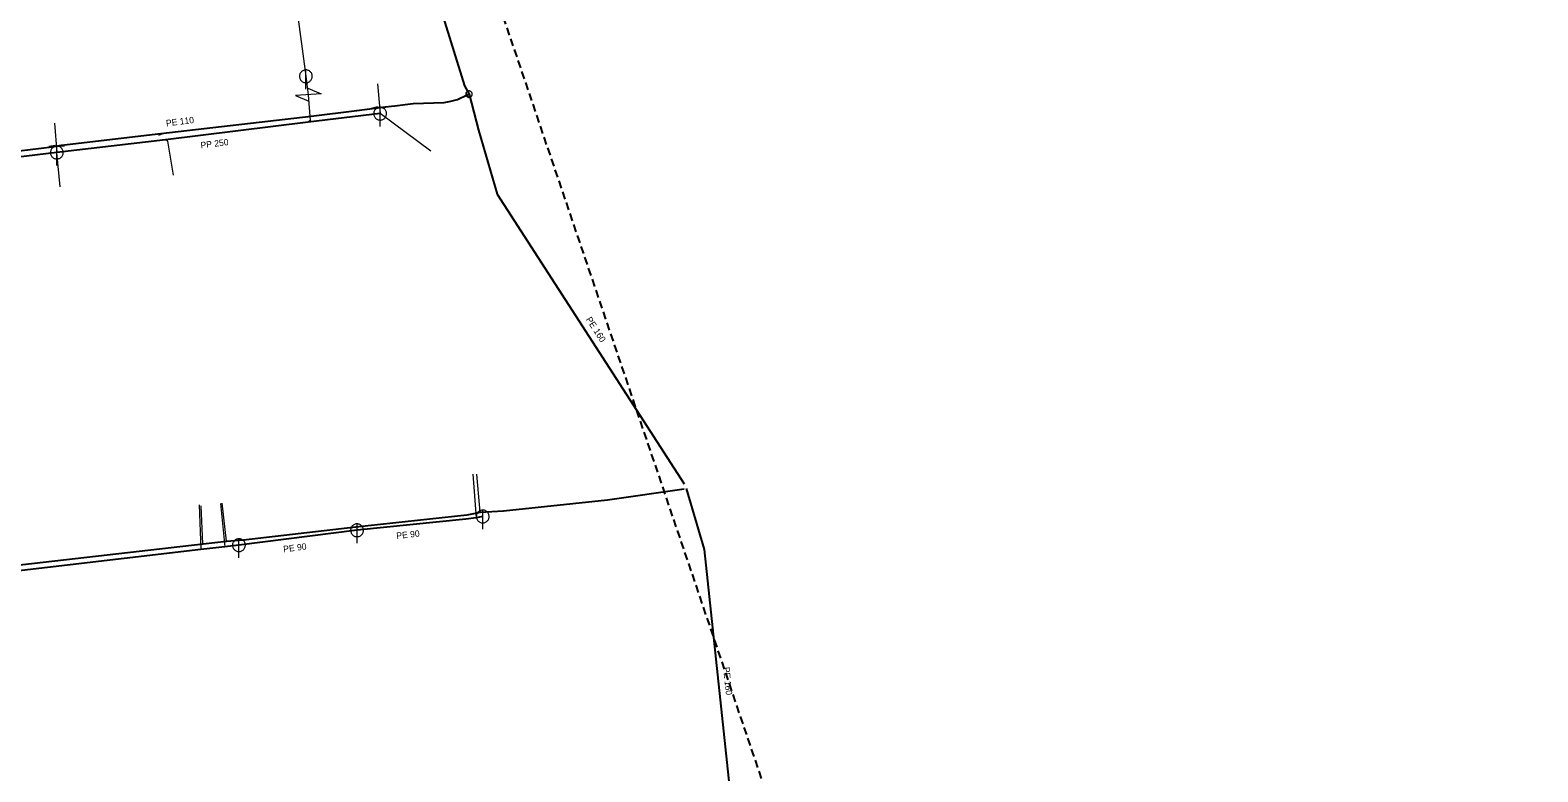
# Model space of a CAD drawing. Extents: x -659250 to -657316, y -997555 to -993684.
# Drawn here: x -658279.6 to -658044.4, y -994985.4 to -994869.8 of the extents above; entities that cross this region are included whole.
import ezdxf

# ---------------------------------------------------------------- set-up
doc = ezdxf.new("R2010")
doc.units = 0
doc.header["$LTSCALE"] = 0.4
doc.linetypes.add('MEDIUM_DASHED', pattern=[4.5, 3, -1.5])
doc.layers.add('1', color=7, linetype='Continuous')
for name, color, linetype, lineweight in [('11', 7, 'Continuous', 13), ('13', 7, 'Continuous', 13), ('14', 7, 'Continuous', 25), ('17', 7, 'Continuous', 25), ('22', 7, 'Continuous', 13), ('31', 7, 'Continuous', 13), ('34', 7, 'Continuous', 13), ('47', 7, 'Continuous', 13), ('63', 7, 'MEDIUM_DASHED', 25)]:
    doc.layers.add(name, color=color, linetype=linetype, lineweight=lineweight)

msp = doc.modelspace()

# ---------------------------------------------------------------- linework, layer by layer
at = {"layer": '11'}
for p, q in [((-658225.43, -994878.129), (-658225, -994882.78)), ((-658217.069, -994888.629), (-658225, -994882.78)), ((-658275.8, -994884.28), (-658275.439, -994888.85)), ((-658274.93, -994894.21), (-658275.439, -994888.85)), ((-658210.52, -994939), (-658210.03, -994945.8)), ((-658253.219, -994943.8), (-658252.949, -994950.76)), ((-658249.899, -994943.55), (-658249.23, -994950.34))]:
    msp.add_line(p, q, dxfattribs=at)
for points in [[(-658222.92, -994831.17), (-658224.469, -994832.109), (-658240.399, -994848.02), (-658240.329, -994849.02), (-658236.579, -994876.96), (-658236.199, -994879.82)], [(-658236.199, -994879.82), (-658235.91, -994883.829), (-658236.23, -994884.129)], [(-658257.25, -994892.359), (-658258.109, -994887.09), (-658258.48, -994886.879)]]:
    msp.add_lwpolyline(points, dxfattribs=at)
at = {"layer": '13'}
for p, q in [((-658209.404, -994944.93), (-658209.899, -994938.989)), ((-658252.632, -994949.85), (-658252.94, -994943.93)), ((-658248.985, -994949.47), (-658249.62, -994943.51))]:
    msp.add_line(p, q, dxfattribs=at)
at = {"layer": '14', "lineweight": 13}
for p, q in [((-658211.41, -994879.859), (-658211.129, -994879.739)), ((-658225.819, -994881.93), (-658225.85, -994881.809)), ((-658224.199, -994881.739), (-658224.17, -994881.829)), ((-658259.189, -994885.859), (-658259.129, -994886.01)), ((-658276.16, -994887.96), (-658276.189, -994887.76)), ((-658274.73, -994887.69), (-658274.719, -994887.87)), ((-658209.399, -994944.98), (-658209.404, -994944.93)), ((-658248.98, -994949.52), (-658248.985, -994949.47)), ((-658252.629, -994949.899), (-658252.632, -994949.85))]:
    msp.add_line(p, q, dxfattribs=at)
at = {"layer": '14'}
for p, q in [((-658275.439, -994888.85), (-658324.8, -994894.71)), ((-658228.6, -994947.75), (-658247.02, -994950.07))]:
    msp.add_line(p, q, dxfattribs=at)
for points in [[(-658225, -994882.78), (-658236.23, -994884.129), (-658258.48, -994886.879), (-658275.439, -994888.85)], [(-658208.989, -994945.6), (-658209.21, -994945.629), (-658210.03, -994945.8), (-658211.649, -994946.02), (-658228.6, -994947.75)], [(-658247.02, -994950.07), (-658249.23, -994950.34), (-658252.949, -994950.76), (-658325.67, -994959.25), (-658326.51, -994959.379)]]:
    msp.add_lwpolyline(points, dxfattribs=at)
at = {"layer": '17'}
for points in [[(-658233.758, -994810.635), (-658224.664, -994837.073), (-658211.84, -994878.42), (-658211.129, -994879.739)], [(-658386.698, -994900.514), (-658384.77, -994900.37), (-658365.6, -994898.41), (-658348.03, -994896.329), (-658347.76, -994896.26), (-658329.91, -994894.239), (-658325.91, -994893.8), (-658324.05, -994893.6), (-658323.85, -994893.6), (-658289.96, -994889.62), (-658276.16, -994887.96), (-658274.73, -994887.69), (-658259.189, -994885.859), (-658235.76, -994883.17), (-658228.649, -994882.27), (-658225.819, -994881.93), (-658224.199, -994881.739), (-658222.71, -994881.559), (-658219.819, -994881.199), (-658214.989, -994881.03), (-658213.939, -994880.859), (-658212.899, -994880.57), (-658211.41, -994879.859)], [(-658211.129, -994879.739), (-658209.67, -994885.379), (-658206.719, -994895.329), (-658177.539, -994940.51)], [(-658177.55, -994941.32), (-658189.53, -994943.03), (-658205.77, -994944.76), (-658209.399, -994944.98), (-658211.489, -994945.399), (-658228.809, -994947.239), (-658246.329, -994949.289), (-658248.98, -994949.52), (-658252.629, -994949.899), (-658327.539, -994958.51), (-658328.37, -994958.84), (-658335.949, -994959.67), (-658349.42, -994961.289), (-658363.318, -994963.144)], [(-658177.25, -994941.239), (-658174.441, -994950.724), (-658169.87, -994993.71)]]:
    msp.add_lwpolyline(points, dxfattribs=at)
at = {"layer": '22'}
for p, q in [((-658236.579, -994878.96), (-658236.578, -994875.96)), ((-658225, -994884.78), (-658224.999, -994881.78)), ((-658275.439, -994890.85), (-658275.438, -994887.85)), ((-658208.989, -994947.6), (-658208.988, -994944.6)), ((-658228.6, -994949.75), (-658228.599, -994946.75)), ((-658247.02, -994952.07), (-658247.019, -994949.07))]:
    msp.add_line(p, q, dxfattribs=at)
for points in [[(-658235.579, -994876.96), (-658235.584, -994876.851), (-658235.602, -994876.743), (-658235.632, -994876.637), (-658235.672, -994876.536), (-658235.724, -994876.439), (-658235.786, -994876.349), (-658235.858, -994876.266), (-658235.938, -994876.192), (-658236.026, -994876.126), (-658236.12, -994876.071), (-658236.22, -994876.026), (-658236.325, -994875.993), (-658236.432, -994875.971), (-658236.541, -994875.961), (-658236.651, -994875.963), (-658236.759, -994875.977), (-658236.866, -994876.002), (-658236.969, -994876.039), (-658237.067, -994876.088), (-658237.159, -994876.146), (-658237.245, -994876.215), (-658237.322, -994876.292), (-658237.391, -994876.378), (-658237.45, -994876.47), (-658237.498, -994876.568), (-658237.535, -994876.671), (-658237.561, -994876.778), (-658237.575, -994876.886), (-658237.578, -994876.996), (-658237.568, -994877.105), (-658237.547, -994877.212), (-658237.513, -994877.316), (-658237.469, -994877.416), (-658237.414, -994877.511), (-658237.348, -994877.599), (-658237.274, -994877.679), (-658237.191, -994877.751), (-658237.101, -994877.813), (-658237.005, -994877.865), (-658236.903, -994877.906), (-658236.798, -994877.936), (-658236.69, -994877.954), (-658236.58, -994877.96), (-658236.471, -994877.954), (-658236.363, -994877.936), (-658236.258, -994877.907), (-658236.156, -994877.866), (-658236.059, -994877.814), (-658235.969, -994877.752), (-658235.886, -994877.681), (-658235.811, -994877.601), (-658235.746, -994877.513), (-658235.69, -994877.419), (-658235.646, -994877.319), (-658235.612, -994877.215), (-658235.59, -994877.107), (-658235.58, -994876.998)], [(-658224, -994882.78), (-658224.005, -994882.671), (-658224.023, -994882.563), (-658224.053, -994882.457), (-658224.093, -994882.356), (-658224.145, -994882.259), (-658224.207, -994882.169), (-658224.279, -994882.086), (-658224.359, -994882.012), (-658224.447, -994881.946), (-658224.541, -994881.891), (-658224.641, -994881.846), (-658224.746, -994881.813), (-658224.853, -994881.791), (-658224.962, -994881.781), (-658225.072, -994881.783), (-658225.18, -994881.797), (-658225.287, -994881.822), (-658225.39, -994881.859), (-658225.488, -994881.908), (-658225.58, -994881.966), (-658225.666, -994882.035), (-658225.743, -994882.112), (-658225.812, -994882.198), (-658225.871, -994882.29), (-658225.919, -994882.388), (-658225.956, -994882.491), (-658225.982, -994882.598), (-658225.996, -994882.706), (-658225.999, -994882.816), (-658225.989, -994882.925), (-658225.968, -994883.032), (-658225.934, -994883.136), (-658225.89, -994883.236), (-658225.835, -994883.331), (-658225.769, -994883.419), (-658225.695, -994883.499), (-658225.612, -994883.571), (-658225.522, -994883.633), (-658225.426, -994883.685), (-658225.324, -994883.726), (-658225.219, -994883.756), (-658225.111, -994883.774), (-658225.001, -994883.78), (-658224.892, -994883.774), (-658224.784, -994883.756), (-658224.679, -994883.727), (-658224.577, -994883.686), (-658224.48, -994883.634), (-658224.39, -994883.572), (-658224.307, -994883.501), (-658224.232, -994883.421), (-658224.167, -994883.333), (-658224.111, -994883.239), (-658224.067, -994883.139), (-658224.033, -994883.035), (-658224.011, -994882.927), (-658224.001, -994882.818)], [(-658274.439, -994888.85), (-658274.444, -994888.741), (-658274.462, -994888.633), (-658274.492, -994888.527), (-658274.532, -994888.426), (-658274.584, -994888.329), (-658274.646, -994888.239), (-658274.718, -994888.156), (-658274.798, -994888.082), (-658274.886, -994888.016), (-658274.98, -994887.961), (-658275.08, -994887.916), (-658275.185, -994887.883), (-658275.292, -994887.861), (-658275.401, -994887.851), (-658275.511, -994887.853), (-658275.619, -994887.867), (-658275.726, -994887.892), (-658275.829, -994887.929), (-658275.927, -994887.978), (-658276.019, -994888.036), (-658276.105, -994888.105), (-658276.182, -994888.182), (-658276.251, -994888.268), (-658276.31, -994888.36), (-658276.358, -994888.458), (-658276.395, -994888.561), (-658276.421, -994888.668), (-658276.435, -994888.776), (-658276.438, -994888.886), (-658276.428, -994888.995), (-658276.407, -994889.102), (-658276.373, -994889.206), (-658276.329, -994889.306), (-658276.274, -994889.401), (-658276.208, -994889.489), (-658276.134, -994889.569), (-658276.051, -994889.641), (-658275.961, -994889.703), (-658275.865, -994889.755), (-658275.763, -994889.796), (-658275.658, -994889.826), (-658275.55, -994889.844), (-658275.44, -994889.85), (-658275.331, -994889.844), (-658275.223, -994889.826), (-658275.118, -994889.797), (-658275.016, -994889.756), (-658274.919, -994889.704), (-658274.829, -994889.642), (-658274.746, -994889.571), (-658274.671, -994889.491), (-658274.606, -994889.403), (-658274.55, -994889.309), (-658274.506, -994889.209), (-658274.472, -994889.105), (-658274.45, -994888.997), (-658274.44, -994888.888)], [(-658207.989, -994945.6), (-658207.994, -994945.491), (-658208.012, -994945.383), (-658208.042, -994945.277), (-658208.082, -994945.176), (-658208.134, -994945.079), (-658208.196, -994944.989), (-658208.268, -994944.906), (-658208.348, -994944.832), (-658208.436, -994944.766), (-658208.53, -994944.711), (-658208.63, -994944.666), (-658208.735, -994944.633), (-658208.842, -994944.611), (-658208.951, -994944.601), (-658209.061, -994944.603), (-658209.169, -994944.617), (-658209.276, -994944.642), (-658209.379, -994944.679), (-658209.477, -994944.728), (-658209.569, -994944.786), (-658209.655, -994944.855), (-658209.732, -994944.932), (-658209.801, -994945.018), (-658209.86, -994945.11), (-658209.908, -994945.208), (-658209.945, -994945.311), (-658209.971, -994945.418), (-658209.985, -994945.526), (-658209.988, -994945.636), (-658209.978, -994945.745), (-658209.957, -994945.852), (-658209.923, -994945.956), (-658209.879, -994946.056), (-658209.824, -994946.151), (-658209.758, -994946.239), (-658209.684, -994946.319), (-658209.601, -994946.391), (-658209.511, -994946.453), (-658209.415, -994946.505), (-658209.313, -994946.546), (-658209.208, -994946.576), (-658209.1, -994946.594), (-658208.99, -994946.6), (-658208.881, -994946.594), (-658208.773, -994946.576), (-658208.668, -994946.547), (-658208.566, -994946.506), (-658208.469, -994946.454), (-658208.379, -994946.392), (-658208.296, -994946.321), (-658208.221, -994946.241), (-658208.156, -994946.153), (-658208.1, -994946.059), (-658208.056, -994945.959), (-658208.022, -994945.855), (-658208, -994945.747), (-658207.99, -994945.638)], [(-658227.6, -994947.75), (-658227.605, -994947.641), (-658227.623, -994947.533), (-658227.653, -994947.427), (-658227.693, -994947.326), (-658227.745, -994947.229), (-658227.807, -994947.139), (-658227.879, -994947.056), (-658227.959, -994946.982), (-658228.047, -994946.916), (-658228.141, -994946.861), (-658228.241, -994946.816), (-658228.346, -994946.783), (-658228.453, -994946.761), (-658228.562, -994946.751), (-658228.672, -994946.753), (-658228.78, -994946.767), (-658228.887, -994946.792), (-658228.99, -994946.829), (-658229.088, -994946.878), (-658229.18, -994946.936), (-658229.266, -994947.005), (-658229.343, -994947.082), (-658229.412, -994947.168), (-658229.471, -994947.26), (-658229.519, -994947.358), (-658229.556, -994947.461), (-658229.582, -994947.568), (-658229.596, -994947.676), (-658229.599, -994947.786), (-658229.589, -994947.895), (-658229.568, -994948.002), (-658229.534, -994948.106), (-658229.49, -994948.206), (-658229.435, -994948.301), (-658229.369, -994948.389), (-658229.295, -994948.469), (-658229.212, -994948.541), (-658229.122, -994948.603), (-658229.026, -994948.655), (-658228.924, -994948.696), (-658228.819, -994948.726), (-658228.711, -994948.744), (-658228.601, -994948.75), (-658228.492, -994948.744), (-658228.384, -994948.726), (-658228.279, -994948.697), (-658228.177, -994948.656), (-658228.08, -994948.604), (-658227.99, -994948.542), (-658227.907, -994948.471), (-658227.832, -994948.391), (-658227.767, -994948.303), (-658227.711, -994948.209), (-658227.667, -994948.109), (-658227.633, -994948.005), (-658227.611, -994947.897), (-658227.601, -994947.788)], [(-658246.02, -994950.07), (-658246.025, -994949.961), (-658246.043, -994949.853), (-658246.073, -994949.747), (-658246.113, -994949.646), (-658246.165, -994949.549), (-658246.227, -994949.459), (-658246.299, -994949.376), (-658246.379, -994949.302), (-658246.467, -994949.236), (-658246.561, -994949.181), (-658246.661, -994949.136), (-658246.766, -994949.103), (-658246.873, -994949.081), (-658246.982, -994949.071), (-658247.092, -994949.073), (-658247.2, -994949.087), (-658247.307, -994949.112), (-658247.41, -994949.149), (-658247.508, -994949.198), (-658247.6, -994949.256), (-658247.686, -994949.325), (-658247.763, -994949.402), (-658247.832, -994949.488), (-658247.891, -994949.58), (-658247.939, -994949.678), (-658247.976, -994949.781), (-658248.002, -994949.888), (-658248.016, -994949.996), (-658248.019, -994950.106), (-658248.009, -994950.215), (-658247.988, -994950.322), (-658247.954, -994950.426), (-658247.91, -994950.526), (-658247.855, -994950.621), (-658247.789, -994950.709), (-658247.715, -994950.789), (-658247.632, -994950.861), (-658247.542, -994950.923), (-658247.446, -994950.975), (-658247.344, -994951.016), (-658247.239, -994951.046), (-658247.131, -994951.064), (-658247.021, -994951.07), (-658246.912, -994951.064), (-658246.804, -994951.046), (-658246.699, -994951.017), (-658246.597, -994950.976), (-658246.5, -994950.924), (-658246.41, -994950.862), (-658246.327, -994950.791), (-658246.252, -994950.711), (-658246.187, -994950.623), (-658246.131, -994950.529), (-658246.087, -994950.429), (-658246.053, -994950.325), (-658246.031, -994950.217), (-658246.021, -994950.108)]]:
    msp.add_lwpolyline(points, close=True, dxfattribs=at)
at = {"layer": '31'}
msp.add_lwpolyline([(-658236.271, -994878.822), (-658234.204, -994879.675), (-658238.194, -994879.964), (-658236.127, -994880.817)], dxfattribs=at)
at = {"layer": '34'}
for p, q in [((-658211.625, -994879.407), (-658211.195, -994880.31)), ((-658226.334, -994881.931), (-658225.364, -994881.687)), ((-658223.695, -994881.67), (-658224.644, -994881.986)), ((-658258.664, -994885.824), (-658259.593, -994886.194)), ((-658276.683, -994887.834), (-658275.694, -994887.686)), ((-658274.219, -994887.841), (-658275.218, -994887.897)), ((-658209.902, -994944.972), (-658208.905, -994944.888)), ((-658249.482, -994949.523), (-658248.487, -994949.417)), ((-658253.131, -994949.876), (-658252.132, -994949.824))]:
    msp.add_line(p, q, dxfattribs=at)
at = {"layer": '47'}
for points in [[(-658210.629, -994879.739), (-658210.632, -994879.686), (-658210.64, -994879.634), (-658210.654, -994879.585), (-658210.671, -994879.536), (-658210.696, -994879.489), (-658210.725, -994879.445), (-658210.757, -994879.404), (-658210.794, -994879.367), (-658210.835, -994879.335), (-658210.879, -994879.306), (-658210.926, -994879.281), (-658210.975, -994879.264), (-658211.024, -994879.25), (-658211.076, -994879.242), (-658211.129, -994879.239), (-658211.181, -994879.242), (-658211.233, -994879.25), (-658211.284, -994879.264), (-658211.331, -994879.281), (-658211.379, -994879.306), (-658211.423, -994879.335), (-658211.463, -994879.367), (-658211.5, -994879.404), (-658211.534, -994879.445), (-658211.561, -994879.489), (-658211.586, -994879.536), (-658211.605, -994879.585), (-658211.617, -994879.634), (-658211.625, -994879.686), (-658211.629, -994879.739), (-658211.625, -994879.791), (-658211.617, -994879.843), (-658211.605, -994879.894), (-658211.586, -994879.941), (-658211.561, -994879.989), (-658211.534, -994880.032), (-658211.5, -994880.073), (-658211.463, -994880.11), (-658211.423, -994880.144), (-658211.379, -994880.171), (-658211.331, -994880.196), (-658211.284, -994880.215), (-658211.233, -994880.227), (-658211.181, -994880.235), (-658211.129, -994880.239), (-658211.076, -994880.235), (-658211.024, -994880.227), (-658210.975, -994880.215), (-658210.926, -994880.196), (-658210.879, -994880.171), (-658210.835, -994880.144), (-658210.794, -994880.11), (-658210.757, -994880.073), (-658210.725, -994880.032), (-658210.696, -994879.989), (-658210.671, -994879.941), (-658210.654, -994879.894), (-658210.64, -994879.843), (-658210.632, -994879.791)], [(-658211.046, -994879.739), (-658211.046, -994879.73), (-658211.049, -994879.722), (-658211.051, -994879.713), (-658211.054, -994879.705), (-658211.058, -994879.698), (-658211.063, -994879.691), (-658211.068, -994879.683), (-658211.073, -994879.678), (-658211.081, -994879.673), (-658211.088, -994879.668), (-658211.095, -994879.664), (-658211.103, -994879.661), (-658211.112, -994879.659), (-658211.12, -994879.656), (-658211.129, -994879.656), (-658211.137, -994879.656), (-658211.146, -994879.659), (-658211.154, -994879.661), (-658211.162, -994879.664), (-658211.169, -994879.668), (-658211.176, -994879.673), (-658211.184, -994879.678), (-658211.19, -994879.683), (-658211.196, -994879.691), (-658211.2, -994879.698), (-658211.203, -994879.705), (-658211.206, -994879.713), (-658211.208, -994879.722), (-658211.211, -994879.73), (-658211.211, -994879.739), (-658211.211, -994879.747), (-658211.208, -994879.755), (-658211.206, -994879.764), (-658211.203, -994879.772), (-658211.2, -994879.779), (-658211.196, -994879.786), (-658211.19, -994879.794), (-658211.184, -994879.799), (-658211.176, -994879.806), (-658211.169, -994879.809), (-658211.162, -994879.813), (-658211.154, -994879.816), (-658211.146, -994879.818), (-658211.137, -994879.821), (-658211.129, -994879.821), (-658211.12, -994879.821), (-658211.112, -994879.818), (-658211.103, -994879.816), (-658211.095, -994879.813), (-658211.088, -994879.809), (-658211.081, -994879.806), (-658211.073, -994879.799), (-658211.068, -994879.794), (-658211.063, -994879.786), (-658211.058, -994879.779), (-658211.054, -994879.772), (-658211.051, -994879.764), (-658211.049, -994879.755), (-658211.046, -994879.747)]]:
    msp.add_lwpolyline(points, close=True, dxfattribs=at)
at = {"layer": '63'}
msp.add_lwpolyline([(-659116.685, -993855.266), (-658551.464, -993848.288), (-658551.464, -993848.288), (-657316.352, -997490.822), (-657316.352, -997490.822), (-657839.705, -997490.822), (-657839.705, -997490.822)], close=True, dxfattribs=at)

# ---------------------------------------------------------------- texts
at = {"layer": '1'}
for s, rotation, p in [('PE 110', 7, (-658258.341, -994884.769)), ('PP 250', 7, (-658252.952, -994888.213)), ('PE 160', 303, (-658192.929, -994914.865)), ('PE 90 ', 6, (-658222.41, -994949.113)), ('PE 90 ', 7, (-658240.041, -994951.191)), ('PE 160', 276, (-658171.492, -994969.128))]:
    msp.add_text(s, height=1, rotation=rotation, dxfattribs=at).set_placement(p)

doc.saveas('drawing.dxf')
